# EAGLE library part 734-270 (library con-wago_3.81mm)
Serie 734, Stiftleiste (für Leiterplatten) Einlötstift abgewinkelt 1 x 1 mm / Series 734, Male header (for PCBs) Angled solder pin 1 x 1 mm Polzahl / Pole No.: 10 Rastermaß / Pitch: 3.81 mm Bemessungsspannung / Rated Voltage: 160 V Nennstrom / Nominal Current: 10 A Lötstiftlänge: / Solder Pin Length: 3.8 mm Farbe / Color: orange / orange Stand: 01.01.2012. Die jeweils aktuellen Daten zu diesem Artikel finden Sie in unserem Produktkatalog, den Sie unter www.wago.com einsehen können. As of: 01/01/2012. Please find the newest data for this article in our product catalogue, which can be viewed under www.wago.com.
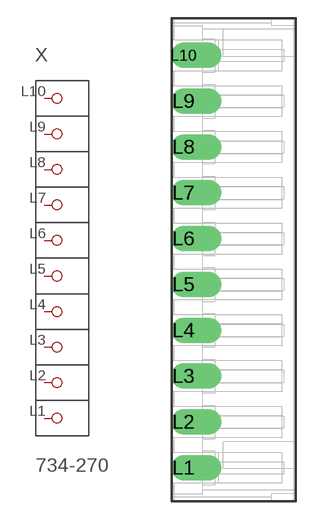
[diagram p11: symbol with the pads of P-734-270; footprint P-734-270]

Designator prefix X

## 734-270  [P-734-270]
L1  P1.1
L2  P2
L3  P3
L4  P4
L5  P5
L6  P6
L7  P7
L8  P8
L9  P9
L10  P10

## Footprint P-734-270 (pad centres in mm)
drill 1.4 pad 2 offset: L1 -4.15,-17.295; L2 -4.15,-13.485; L3 -4.15,-9.675; L4 -4.15,-5.865; L5 -4.15,-2.055; L6 -4.15,1.755; L7 -4.15,5.565; L8 -4.15,9.375; L9 -4.15,13.185; L10 -4.15,16.995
